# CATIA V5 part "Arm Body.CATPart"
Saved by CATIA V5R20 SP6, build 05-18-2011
Part number: Arm Body
Bounding box of the stored display mesh (mm): x 0 to 16, y -5.5 to 5.5, z 0 to 26
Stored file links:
  E:\#03 University\#02 영남 이공대\#01 2021\#02 여름 방학\#01 Documents\K-Move Page02 ASD02\Arm Body.CATPart

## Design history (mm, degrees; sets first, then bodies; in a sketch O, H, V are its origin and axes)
Set1 "Reference Data"
  Point1 "Center Point": (0, 0, 0)
Body1 (main body)
  Body2
    Sketch1 on yz-plane, origin (0, 0, 0), H (0, 1, 0), V (0, 0, 1)
      point P1 (-5.5, 0)
      line L1 (-5.5, 0) -> (5.5, 0)
      line L2 (5.5, 0) -> (5.5, 26)
      line L3 (5.5, 26) -> (-5.5, 26)
      line L4 (-5.5, 26) -> (-5.5, 0)
      distance L4 L2 = 11
      distance L3 H = 26
      coincidence: P1 H
      horizontal: L1 H, L3 H
      vertical: L2 V, L4 V
      symmetry: L4 L2 V
    Pad1: profile Sketch1, direction (1, 0, 0), length 2
  Assemble1: tool Body2
  Body3
    Sketch2 on yz-plane, origin (0, 0, 0), H (0, 1, 0), V (0, 0, 1)
      construction arc A1 centre (0, -23) radius 30 from (5.5, 6.4915) to (-5.5, 6.4915) ccw
      point P1 (0, -23)
      point P2 (5.5, 6.4915)
      point P3 (-5.5, 6.4915)
      arc A2 centre (0, -23) radius 34 from (5.5, 10.5522) to (-5.5, 10.5522) ccw
      point P4 (6.2333, 10.4237)
      point P5 (-6.2333, 10.4237)
      construction line L1 (5.5, 6.4915) -> (6.2333, 10.4237)
      construction line L2 (-5.5, 6.4915) -> (-6.2333, 10.4237)
      arc A3 centre (0, -23) radius 26 from (5.5, 2.4116) to (-5.5, 2.4116) ccw
      point P6 (4.7667, 2.5593)
      point P7 (-4.7667, 2.5593)
      construction line L3 (5.5, 6.4915) -> (4.7667, 2.5593)
      construction line L4 (-5.5, 6.4915) -> (-4.7667, 2.5593)
      projected line E1 (-5.5, 26) -> (-5.5, 0) from edge [face of Pad1 from Sketch1.L4 | end face of Pad1]
      projected line E2 (-5.5, 10.5522) -> (-5.5, 2.4116) from edge [face of Pad1 from Sketch1.L4 | end face of Pad1]
      projected line E3 (5.5, 0) -> (5.5, 26) from edge [face of Pad1 from Sketch1.L2 | end face of Pad1]
      projected line E4 (5.5, 2.4116) -> (5.5, 10.5522) from edge [face of Pad1 from Sketch1.L2 | end face of Pad1]
      radius A1 = 30
      distance H A1 = 7
      distance A1 A2 = 4
      distance A1 A3 = 4
      coincidence: P1 V, L1 P1, L2 P1, L3 P1, L4 P1, P5 A2, P4 A2, P6 A3, P7 A3, P3 E1, P2 E3
      concentricity: A1 A2, A1 A3
    Pad2: profile Sketch2, direction (1, 0, 0), length 16
  Assemble2: tool Body3
  Body4 "Hole Body(M4)"
    Sketch3 on yz-plane, origin (0, 0, 0), H (0, 1, 0), V (0, 0, 1)
      construction circle A1 centre (0, -23) radius 30
      point P1 (0, -23)
      circle A2 centre (0, 7) radius 2
      point P2 (0, 7)
      radius A1 = 30
      distance P1 H = 23
      radius A2 = 2
      coincidence: P1 V, P2 A1, P2 V
    Pad3: profile Sketch3, direction (1, 0, 0), length 20
  Remove1: tool Body4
